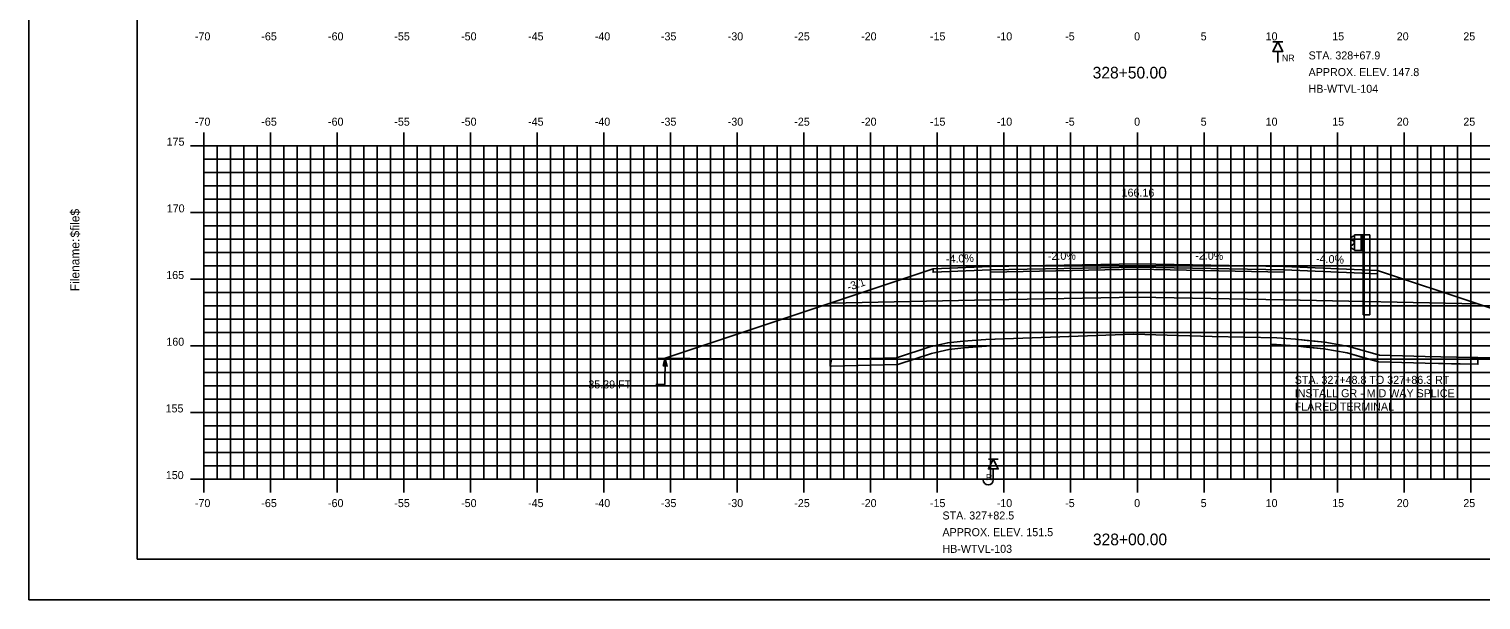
# Model space of a CAD drawing. Extents: x 1140981 to 1141151, y 608981 to 609091.
# Drawn here: x 1140980.7 to 1141089.5, y 608981.3 to 609024.1 of the extents above; entities that cross this region are included whole.
import ezdxf

# ---------------------------------------------------------------- set-up
doc = ezdxf.new("R2010")
doc.units = 0
for name, color, linetype in [('ANNOTATION', 7, 'Continuous'), ('BORDER', 7, 'Continuous'), ('D_Guardrail_Beam_Rt', 7, 'Continuous'), ('D_Guardrail_ConcBarrier', 7, 'Continuous'), ('D_Roadway_Centerline', 7, 'Continuous'), ('D_Roadway_Centerline_Text', 7, 'Continuous'), ('D_Roadway_Edge_Shoulder', 7, 'Continuous'), ('D_Roadway_Edge_TW', 7, 'Continuous'), ('D_Roadway_Pavement', 7, 'Continuous'), ('D_Roadway_SlopeLines', 7, 'Continuous'), ('D_Roadway_SubGrade', 7, 'Continuous'), ('D_Text_Standard', 7, 'Continuous'), ('H_V ANNOTATION', 7, 'Continuous'), ('MAJOR', 7, 'Continuous'), ('MINOR', 7, 'Continuous'), ('PLOT BOUNDARY', 7, 'Continuous'), ('ROCKS', 7, 'Continuous'), ('S_Roadway_Centerline', 7, 'Continuous'), ('SHADING', 7, 'Continuous')]:
    doc.layers.add(name, color=color, linetype=linetype)

msp = doc.modelspace()

# ---------------------------------------------------------------- linework, layer by layer
msp.add_lwpolyline([(1141028.37, 608999.41), (1141037.74, 609002.53), (1141040.74, 609003.53), (1141048.45, 609006.1), (1141048.45, 609006.1), (1141052.76, 609006.27), (1141063.76, 609006.49), (1141074.76, 609006.27), (1141081.76, 609005.99), (1141089.29, 609003.48), (1141092.29, 609002.48), (1141100.31, 608999.81)])
at = {"layer": 'BORDER'}
msp.add_lwpolyline([(1140988.76, 608984.34), (1141148.76, 608984.34), (1141148.76, 609089.34), (1140988.76, 609089.34)], close=True, dxfattribs=at)
at = {"layer": 'D_Guardrail_Beam_Rt'}
for p, q in [((1141079.94, 609008.55), (1141079.79, 609008.45)), ((1141079.79, 609008.31), (1141079.99, 609008.17)), ((1141080.03, 609008.57), (1141079.95, 609008.56)), ((1141079.99, 609007.97), (1141079.79, 609007.84)), ((1141079.79, 609007.69), (1141079.94, 609007.59)), ((1141079.95, 609007.59), (1141080.03, 609007.57)), ((1141080.02, 609008.11), (1141080.02, 609008.04))]:
    msp.add_line(p, q, dxfattribs=at)
for centre, major_axis, start_param, end_param in [((1141079.85, 609008.38), (-0.0877, 0), 5.323254, 7.243116), ((1141079.96, 609008.52), (-0.0417, 0), 4.907132, 5.323254), ((1141079.85, 609007.77), (-0.0877, 0), 5.323254, 7.243116), ((1141079.96, 609007.63), (-0.0417, 0), 0.959931, 1.376053), ((1141079.95, 609008.11), (0.0789, 0), 0, 0.959931), ((1141079.95, 609008.04), (0.0789, 0), 5.323254, 6.283185)]:
    msp.add_ellipse(centre, major_axis=major_axis, ratio=0.995501, start_param=start_param, end_param=end_param, dxfattribs=at)
at = {"layer": 'D_Guardrail_ConcBarrier'}
for p, q in [((1141080.03, 609008.66), (1141080.72, 609008.66)), ((1141080.03, 609007.49), (1141080.03, 609008.66)), ((1141080.55, 609008.66), (1141080.55, 609007.49)), ((1141080.65, 609008.66), (1141080.65, 609007.49)), ((1141080.72, 609008.66), (1141081.19, 609008.66)), ((1141080.72, 609008.66), (1141080.72, 609007.49)), ((1141081.19, 609008.66), (1141081.19, 609002.66)), ((1141080.72, 609007.49), (1141080.03, 609007.49)), ((1141080.7, 609002.66), (1141080.7, 609007.49)), ((1141080.7, 609002.66), (1141081.19, 609002.66))]:
    msp.add_line(p, q, dxfattribs=at)
at = {"layer": 'D_Roadway_Edge_Shoulder'}
for points in [[(1141052.76, 609006.27), (1141048.45, 609006.1), (1141048.45, 609005.85), (1141052.76, 609006.02)], [(1141074.76, 609006.27), (1141081.76, 609005.99), (1141081.76, 609005.74), (1141074.76, 609006.02)]]:
    msp.add_lwpolyline(points, close=True, dxfattribs=at)
at = {"layer": 'D_Roadway_Edge_TW'}
msp.add_lwpolyline([(1141052.76, 609006.02), (1141052.76, 609006.27), (1141063.76, 609006.49), (1141074.76, 609006.27), (1141074.76, 609006.02), (1141063.76, 609006.24)], close=True, dxfattribs=at)
at = {"layer": 'D_Roadway_Pavement'}
msp.add_lwpolyline([(1141052.76, 609005.86), (1141052.76, 609006.02), (1141063.76, 609006.24), (1141074.76, 609006.02), (1141074.76, 609005.86), (1141063.76, 609006.08)], close=True, dxfattribs=at)
at = {"layer": 'D_Roadway_SlopeLines'}
for p, q in [((1141053.76, 609000.87), (1141053.76, 609000.37)), ((1141073.76, 609000.95), (1141073.76, 609000.45)), ((1141040.74, 608999.3), (1141040.74, 608998.8)), ((1141089.29, 608999.45), (1141089.29, 608998.95))]:
    msp.add_line(p, q, dxfattribs=at)
for points in [[(1141040.74, 609003.53), (1141037.74, 609002.53)], [(1141089.29, 609003.48), (1141092.29, 609002.48)], [(1141037.74, 609002.53), (1141028.37, 608999.41)], [(1141040.74, 608998.8), (1141040.83, 608998.8), (1141045.8, 608998.94), (1141048.32, 608999.77), (1141049.63, 609000.07), (1141050.76, 609000.19), (1141052.44, 609000.32), (1141053.76, 609000.37)], [(1141073.76, 609000.45), (1141074.2, 609000.44), (1141075.58, 609000.33), (1141077.75, 609000.11), (1141079.5, 608999.8), (1141081.84, 608999.13), (1141085.34, 608999.03), (1141089.29, 608998.95)]]:
    msp.add_lwpolyline(points, dxfattribs=at)
at = {"layer": 'D_Roadway_SubGrade'}
for points in [[(1141052.76, 609005.86), (1141052.76, 609006.02), (1141048.45, 609005.85), (1141048.45, 609006.1), (1141048.45, 609006.1), (1141040.74, 609003.53), (1141052.76, 609003.77)], [(1141052.76, 609003.77), (1141052.76, 609005.86), (1141063.76, 609006.08), (1141074.76, 609005.86), (1141074.76, 609003.77), (1141063.76, 609003.99)], [(1141074.76, 609005.86), (1141074.76, 609006.02), (1141081.76, 609005.74), (1141081.76, 609005.99), (1141081.76, 609005.99), (1141089.29, 609003.48), (1141074.76, 609003.77)]]:
    msp.add_lwpolyline(points, close=True, dxfattribs=at)
at = {"layer": 'D_Text_Standard'}
msp.add_lwpolyline([(1141028.37, 608999.41), (1141028.34, 608997.44), (1141027.66, 608997.44)], dxfattribs=at)
msp.add_lwpolyline([(1141028.37, 608999.41), (1141028.51, 608998.82), (1141028.22, 608998.83)], close=True, dxfattribs=at)
at = {"layer": 'MAJOR'}
for p, q in [((1140993.76, 609016.34), (1140993.76, 609015.34)), ((1140998.76, 609016.34), (1140998.76, 609015.34)), ((1141003.76, 609016.34), (1141003.76, 609015.34)), ((1141008.76, 609016.34), (1141008.76, 609015.34)), ((1141013.76, 609016.34), (1141013.76, 609015.34)), ((1141018.76, 609016.34), (1141018.76, 609015.34)), ((1141023.76, 609016.34), (1141023.76, 609015.34)), ((1141028.76, 609016.34), (1141028.76, 609015.34)), ((1141033.76, 609016.34), (1141033.76, 609015.34)), ((1141038.76, 609016.34), (1141038.76, 609015.34)), ((1141043.76, 609016.34), (1141043.76, 609015.34)), ((1141048.76, 609016.34), (1141048.76, 609015.34)), ((1141053.76, 609016.34), (1141053.76, 609015.34)), ((1141058.76, 609016.34), (1141058.76, 609015.34)), ((1141063.76, 609016.34), (1141063.76, 609015.34)), ((1141068.76, 609016.34), (1141068.76, 609015.34)), ((1141073.76, 609016.34), (1141073.76, 609015.34)), ((1141078.76, 609016.34), (1141078.76, 609015.34)), ((1141083.76, 609016.34), (1141083.76, 609015.34)), ((1141088.76, 609016.34), (1141088.76, 609015.34)), ((1140992.76, 609015.34), (1140993.76, 609015.34)), ((1140993.76, 609015.34), (1141133.76, 609015.34)), ((1140993.76, 608990.34), (1140993.76, 609015.34)), ((1140993.76, 608990.34), (1140993.76, 609015.34)), ((1140993.76, 609015.34), (1141133.76, 609015.34)), ((1140998.76, 608990.34), (1140998.76, 609015.34)), ((1141003.76, 608990.34), (1141003.76, 609015.34)), ((1141008.76, 608990.34), (1141008.76, 609015.34)), ((1141013.76, 608990.34), (1141013.76, 609015.34)), ((1141018.76, 608990.34), (1141018.76, 609015.34)), ((1141023.76, 608990.34), (1141023.76, 609015.34)), ((1141028.76, 608990.34), (1141028.76, 609015.34)), ((1141033.76, 608990.34), (1141033.76, 609015.34)), ((1141038.76, 608990.34), (1141038.76, 609015.34)), ((1141043.76, 608990.34), (1141043.76, 609015.34)), ((1141048.76, 608990.34), (1141048.76, 609015.34)), ((1141053.76, 608990.34), (1141053.76, 609015.34)), ((1141058.76, 608990.34), (1141058.76, 609015.34)), ((1141063.76, 608990.34), (1141063.76, 609015.34)), ((1141068.76, 608990.34), (1141068.76, 609015.34)), ((1141073.76, 608990.34), (1141073.76, 609015.34)), ((1141078.76, 608990.34), (1141078.76, 609015.34)), ((1141083.76, 608990.34), (1141083.76, 609015.34)), ((1141088.76, 608990.34), (1141088.76, 609015.34)), ((1140992.76, 609010.34), (1140993.76, 609010.34)), ((1140993.76, 609010.34), (1141133.76, 609010.34)), ((1140992.76, 609005.34), (1140993.76, 609005.34)), ((1140993.76, 609005.34), (1141133.76, 609005.34)), ((1140992.76, 609000.34), (1140993.76, 609000.34)), ((1140993.76, 609000.34), (1141133.76, 609000.34)), ((1140992.76, 608995.34), (1140993.76, 608995.34)), ((1140993.76, 608995.34), (1141133.76, 608995.34)), ((1140992.76, 608990.34), (1140993.76, 608990.34)), ((1140993.76, 608990.34), (1141133.76, 608990.34)), ((1140993.76, 608990.34), (1141133.76, 608990.34)), ((1140993.76, 608989.33), (1140993.76, 608990.34)), ((1140998.76, 608989.33), (1140998.76, 608990.34)), ((1141003.76, 608989.33), (1141003.76, 608990.34)), ((1141008.76, 608989.33), (1141008.76, 608990.34)), ((1141013.76, 608989.33), (1141013.76, 608990.34)), ((1141018.76, 608989.33), (1141018.76, 608990.34)), ((1141023.76, 608989.33), (1141023.76, 608990.34)), ((1141028.76, 608989.33), (1141028.76, 608990.34)), ((1141033.76, 608989.33), (1141033.76, 608990.34)), ((1141038.76, 608989.33), (1141038.76, 608990.34)), ((1141043.76, 608989.33), (1141043.76, 608990.34)), ((1141048.76, 608989.33), (1141048.76, 608990.34)), ((1141053.76, 608989.33), (1141053.76, 608990.34)), ((1141058.76, 608989.33), (1141058.76, 608990.34)), ((1141063.76, 608989.33), (1141063.76, 608990.34)), ((1141068.76, 608989.33), (1141068.76, 608990.34)), ((1141073.76, 608989.33), (1141073.76, 608990.34)), ((1141078.76, 608989.33), (1141078.76, 608990.34)), ((1141083.76, 608989.33), (1141083.76, 608990.34)), ((1141088.76, 608989.33), (1141088.76, 608990.34))]:
    msp.add_line(p, q, dxfattribs=at)
at = {"layer": 'MINOR'}
for p, q in [((1140994.76, 608990.34), (1140994.76, 609015.34)), ((1140995.76, 608990.34), (1140995.76, 609015.34)), ((1140996.76, 608990.34), (1140996.76, 609015.34)), ((1140997.76, 608990.34), (1140997.76, 609015.34)), ((1140999.76, 608990.34), (1140999.76, 609015.34)), ((1141000.76, 608990.34), (1141000.76, 609015.34)), ((1141001.76, 608990.34), (1141001.76, 609015.34)), ((1141002.76, 608990.34), (1141002.76, 609015.34)), ((1141004.76, 608990.34), (1141004.76, 609015.34)), ((1141005.76, 608990.34), (1141005.76, 609015.34)), ((1141006.76, 608990.34), (1141006.76, 609015.34)), ((1141007.76, 608990.34), (1141007.76, 609015.34)), ((1141009.76, 608990.34), (1141009.76, 609015.34)), ((1141010.76, 608990.34), (1141010.76, 609015.34)), ((1141011.76, 608990.34), (1141011.76, 609015.34)), ((1141012.76, 608990.34), (1141012.76, 609015.34)), ((1141014.76, 608990.34), (1141014.76, 609015.34)), ((1141015.76, 608990.34), (1141015.76, 609015.34)), ((1141016.76, 608990.34), (1141016.76, 609015.34)), ((1141017.76, 608990.34), (1141017.76, 609015.34)), ((1141019.76, 608990.34), (1141019.76, 609015.34)), ((1141020.76, 608990.34), (1141020.76, 609015.34)), ((1141021.76, 608990.34), (1141021.76, 609015.34)), ((1141022.76, 608990.34), (1141022.76, 609015.34)), ((1141024.76, 608990.34), (1141024.76, 609015.34)), ((1141025.76, 608990.34), (1141025.76, 609015.34)), ((1141026.76, 608990.34), (1141026.76, 609015.34)), ((1141027.76, 608990.34), (1141027.76, 609015.34)), ((1141029.76, 608990.34), (1141029.76, 609015.34)), ((1141030.76, 608990.34), (1141030.76, 609015.34)), ((1141031.76, 608990.34), (1141031.76, 609015.34)), ((1141032.76, 608990.34), (1141032.76, 609015.34)), ((1141034.76, 608990.34), (1141034.76, 609015.34)), ((1141035.76, 608990.34), (1141035.76, 609015.34)), ((1141036.76, 608990.34), (1141036.76, 609015.34)), ((1141037.76, 608990.34), (1141037.76, 609015.34)), ((1141039.76, 608990.34), (1141039.76, 609015.34)), ((1141040.76, 608990.34), (1141040.76, 609015.34)), ((1141041.76, 608990.34), (1141041.76, 609015.34)), ((1141042.76, 608990.34), (1141042.76, 609015.34)), ((1141044.76, 608990.34), (1141044.76, 609015.34)), ((1141045.76, 608990.34), (1141045.76, 609015.34)), ((1141046.76, 608990.34), (1141046.76, 609015.34)), ((1141047.76, 608990.34), (1141047.76, 609015.34)), ((1141049.76, 608990.34), (1141049.76, 609015.34)), ((1141050.76, 608990.34), (1141050.76, 609015.34)), ((1141051.76, 608990.34), (1141051.76, 609015.34)), ((1141052.76, 608990.34), (1141052.76, 609015.34)), ((1141054.76, 608990.34), (1141054.76, 609015.34)), ((1141055.76, 608990.34), (1141055.76, 609015.34)), ((1141056.76, 608990.34), (1141056.76, 609015.34)), ((1141057.76, 608990.34), (1141057.76, 609015.34)), ((1141059.76, 608990.34), (1141059.76, 609015.34)), ((1141060.76, 608990.34), (1141060.76, 609015.34)), ((1141061.76, 608990.34), (1141061.76, 609015.34)), ((1141062.76, 608990.34), (1141062.76, 609015.34)), ((1141064.76, 608990.34), (1141064.76, 609015.34)), ((1141065.76, 608990.34), (1141065.76, 609015.34)), ((1141066.76, 608990.34), (1141066.76, 609015.34)), ((1141067.76, 608990.34), (1141067.76, 609015.34)), ((1141069.76, 608990.34), (1141069.76, 609015.34)), ((1141070.76, 608990.34), (1141070.76, 609015.34)), ((1141071.76, 608990.34), (1141071.76, 609015.34)), ((1141072.76, 608990.34), (1141072.76, 609015.34)), ((1141074.76, 608990.34), (1141074.76, 609015.34)), ((1141075.76, 608990.34), (1141075.76, 609015.34)), ((1141076.76, 608990.34), (1141076.76, 609015.34)), ((1141077.76, 608990.34), (1141077.76, 609015.34)), ((1141079.76, 608990.34), (1141079.76, 609015.34)), ((1141080.76, 608990.34), (1141080.76, 609015.34)), ((1141081.76, 608990.34), (1141081.76, 609015.34)), ((1141082.76, 608990.34), (1141082.76, 609015.34)), ((1141084.76, 608990.34), (1141084.76, 609015.34)), ((1141085.76, 608990.34), (1141085.76, 609015.34)), ((1141086.76, 608990.34), (1141086.76, 609015.34)), ((1141087.76, 608990.34), (1141087.76, 609015.34)), ((1140993.76, 609014.34), (1141133.76, 609014.34)), ((1140993.76, 609014.34), (1140994.76, 609014.34)), ((1140993.76, 609013.34), (1141133.76, 609013.34)), ((1140993.76, 609013.34), (1140994.76, 609013.34)), ((1140993.76, 609012.34), (1141133.76, 609012.34)), ((1140993.76, 609012.34), (1140994.76, 609012.34)), ((1140993.76, 609011.34), (1141133.76, 609011.34)), ((1140993.76, 609011.34), (1140994.76, 609011.34)), ((1140993.76, 609009.34), (1141133.76, 609009.34)), ((1140993.76, 609009.34), (1140994.76, 609009.34)), ((1140993.76, 609008.34), (1141133.76, 609008.34)), ((1140993.76, 609008.34), (1140994.76, 609008.34)), ((1140993.76, 609007.34), (1141133.76, 609007.34)), ((1140993.76, 609007.34), (1140994.76, 609007.34)), ((1140993.76, 609006.34), (1141133.76, 609006.34)), ((1140993.76, 609006.34), (1140994.76, 609006.34)), ((1140993.76, 609004.34), (1141133.76, 609004.34)), ((1140993.76, 609004.34), (1140994.76, 609004.34)), ((1140993.76, 609003.34), (1141133.76, 609003.34)), ((1140993.76, 609003.34), (1140994.76, 609003.34)), ((1140993.76, 609002.34), (1141133.76, 609002.34)), ((1140993.76, 609002.34), (1140994.76, 609002.34)), ((1140993.76, 609001.34), (1141133.76, 609001.34)), ((1140993.76, 609001.34), (1140994.76, 609001.34)), ((1140993.76, 608999.34), (1141133.76, 608999.34)), ((1140993.76, 608999.34), (1140994.76, 608999.34)), ((1140993.76, 608998.34), (1141133.76, 608998.34)), ((1140993.76, 608998.34), (1140994.76, 608998.34)), ((1140993.76, 608997.34), (1141133.76, 608997.34)), ((1140993.76, 608997.34), (1140994.76, 608997.34)), ((1140993.76, 608996.34), (1141133.76, 608996.34)), ((1140993.76, 608996.34), (1140994.76, 608996.34)), ((1140993.76, 608994.34), (1141133.76, 608994.34)), ((1140993.76, 608994.34), (1140994.76, 608994.34)), ((1140993.76, 608993.34), (1141133.76, 608993.34)), ((1140993.76, 608993.34), (1140994.76, 608993.34)), ((1140993.76, 608992.34), (1141133.76, 608992.34)), ((1140993.76, 608992.34), (1140994.76, 608992.34)), ((1140993.76, 608991.34), (1141133.76, 608991.34)), ((1140993.76, 608991.34), (1140994.76, 608991.34))]:
    msp.add_line(p, q, dxfattribs=at)
at = {"layer": 'PLOT BOUNDARY'}
msp.add_lwpolyline([(1140980.66, 608981.28), (1141150.66, 608981.28), (1141150.66, 609091.28), (1140980.66, 609091.28)], close=True, dxfattribs=at)
at = {"layer": 'ROCKS'}
for p, q in [((1141074.66, 609023.14), (1141073.92, 609023.14)), ((1141074.29, 609022.4), (1141074.29, 609021.59)), ((1141053.33, 608991.84), (1141052.59, 608991.84)), ((1141052.96, 608991.1), (1141052.96, 608990.28))]:
    msp.add_line(p, q, dxfattribs=at)
for points in [[(1141074.29, 609023.14), (1141074.66, 609022.4), (1141073.92, 609022.4)], [(1141052.96, 608991.84), (1141053.33, 608991.1), (1141052.59, 608991.1)]]:
    msp.add_lwpolyline(points, close=True, dxfattribs=at)
msp.add_arc((1141052.58, 608990.28), 0.373, 180, 0, dxfattribs=at)
at = {"layer": 'S_Roadway_Centerline'}
msp.add_lwpolyline([(1141027.79, 608999.42), (1141035.02, 608999.33), (1141040.82, 608999.3), (1141045.71, 608999.44), (1141048.19, 609000.26), (1141049.55, 609000.56), (1141050.71, 609000.69), (1141052.41, 609000.82), (1141057.26, 609000.98), (1141063.48, 609001.22), (1141069.36, 609001.03), (1141074.22, 609000.94), (1141075.62, 609000.83), (1141077.82, 609000.61), (1141079.61, 609000.29), (1141081.91, 608999.63), (1141085.35, 608999.53), (1141090.01, 608999.43), (1141098.33, 608999.82), (1141111.2, 608999.73)], dxfattribs=at)
at = {"layer": 'SHADING'}
for p, q in [((1141053.76, 609000.37), (1141053.76, 609000.87)), ((1141040.82, 608999.3), (1141040.74, 608998.8))]:
    msp.add_line(p, q, dxfattribs=at)
for points in [[(1141053.76, 609000.87), (1141052.41, 609000.82), (1141050.71, 609000.69), (1141049.55, 609000.56), (1141048.19, 609000.26), (1141045.71, 608999.44), (1141040.82, 608999.3)], [(1141040.74, 608998.8), (1141045.8, 608998.94), (1141048.32, 608999.77), (1141049.63, 609000.07), (1141050.76, 609000.19), (1141052.44, 609000.32), (1141053.76, 609000.37)]]:
    msp.add_lwpolyline(points, dxfattribs=at)
msp.add_lwpolyline([(1141073.76, 609000.95), (1141073.76, 609000.45), (1141074.2, 609000.44), (1141075.58, 609000.33), (1141076.66, 609000.22), (1141077.75, 609000.11), (1141079.5, 608999.8), (1141080.67, 608999.47), (1141081.84, 608999.13), (1141083.59, 608999.08), (1141085.34, 608999.03), (1141087.31, 608998.99), (1141089.29, 608998.95), (1141089.29, 608999.45), (1141087.68, 608999.48), (1141085.35, 608999.53), (1141083.63, 608999.58), (1141081.91, 608999.63), (1141079.61, 609000.29), (1141077.82, 609000.61), (1141076.72, 609000.72), (1141075.62, 609000.83), (1141074.22, 609000.94)], close=True, dxfattribs=at)

# ---------------------------------------------------------------- texts
at = {"layer": 'ANNOTATION'}
for s, rotation, p in [('-4.0%', 2.2906, (1141049.42, 609006.54)), ('-2.0%', 1.1458, (1141057.06, 609006.76)), ('-2.0%', 358.8542, (1141068.1, 609006.81)), ('-4.0%', 357.7094, (1141077.15, 609006.58)), ('-3:1', 18.4348, (1141042.11, 609004.44))]:
    msp.add_text(s, height=0.6, rotation=rotation, dxfattribs=at).set_placement(p)
for s, p in [('STA. 327+48.8 TO 327+86.3 RT', (1141075.56, 608997.48)), ('INSTALL GR - MID WAY SPLICE', (1141075.56, 608996.48)), ('FLARED TERMINAL', (1141075.56, 608995.48))]:
    msp.add_text(s, height=0.6, dxfattribs=at).set_placement(p)
at = {"layer": 'BORDER'}
for s, p in [('$file$', (1140984.44, 609008.46)), ('Filename:', (1140984.44, 609004.43))]:
    msp.add_text(s, height=0.67, rotation=90, dxfattribs=at).set_placement(p)
at = {"layer": 'D_Roadway_Centerline'}
for s, p in [('C', (1141063.75, 609006.49)), ('C', (1141063.75, 609006.49)), ('L', (1141063.76, 609006.49)), ('L', (1141063.76, 609006.49))]:
    msp.add_text(s, height=0.0146, dxfattribs=at).set_placement(p)
at = {"layer": 'D_Roadway_Centerline_Text'}
msp.add_text('166.16', height=0.6, dxfattribs=at).set_placement((1141062.58, 609011.52))
at = {"layer": 'D_Text_Standard'}
msp.add_text('-35.39 FT', height=0.6, dxfattribs=at).set_placement((1141022.33, 608997.14))
at = {"layer": 'H_V ANNOTATION'}
for s, height, p in [('-70', 0.6, (1140993.1, 609023.24)), ('-65', 0.6, (1140998.08, 609023.24)), ('-60', 0.6, (1141003.08, 609023.24)), ('-55', 0.6, (1141008.05, 609023.24)), ('-50', 0.6, (1141013.06, 609023.24)), ('-45', 0.6, (1141018.08, 609023.24)), ('-40', 0.6, (1141023.08, 609023.24)), ('-35', 0.6, (1141028.04, 609023.24)), ('-30', 0.6, (1141033.05, 609023.24)), ('-25', 0.6, (1141038.04, 609023.24)), ('-20', 0.6, (1141043.05, 609023.24)), ('-15', 0.6, (1141048.21, 609023.24)), ('-10', 0.6, (1141053.22, 609023.24)), ('-5', 0.6, (1141058.35, 609023.24)), ('0', 0.6, (1141063.52, 609023.24)), ('5', 0.6, (1141068.51, 609023.24)), ('10', 0.6, (1141073.38, 609023.24)), ('15', 0.6, (1141078.37, 609023.24)), ('20', 0.6, (1141083.21, 609023.24)), ('25', 0.6, (1141088.2, 609023.24)), ('328+50.00', 0.875, (1141060.41, 609020.38)), ('-70', 0.6, (1140993.1, 609016.84)), ('-65', 0.6, (1140998.08, 609016.84)), ('-60', 0.6, (1141003.08, 609016.84)), ('-55', 0.6, (1141008.05, 609016.84)), ('-50', 0.6, (1141013.06, 609016.84)), ('-45', 0.6, (1141018.08, 609016.84)), ('-40', 0.6, (1141023.08, 609016.84)), ('-35', 0.6, (1141028.04, 609016.84)), ('-30', 0.6, (1141033.05, 609016.84)), ('-25', 0.6, (1141038.04, 609016.84)), ('-20', 0.6, (1141043.05, 609016.84)), ('-15', 0.6, (1141048.21, 609016.84)), ('-10', 0.6, (1141053.22, 609016.84)), ('-5', 0.6, (1141058.35, 609016.84)), ('0', 0.6, (1141063.52, 609016.84)), ('5', 0.6, (1141068.51, 609016.84)), ('10', 0.6, (1141073.38, 609016.84)), ('15', 0.6, (1141078.37, 609016.84)), ('20', 0.6, (1141083.21, 609016.84)), ('25', 0.6, (1141088.2, 609016.84)), ('175', 0.6, (1140990.98, 609015.34)), ('170', 0.6, (1140990.99, 609010.34)), ('165', 0.6, (1140990.95, 609005.34)), ('160', 0.6, (1140990.96, 609000.34)), ('155', 0.6, (1140990.9, 608995.34)), ('150', 0.6, (1140990.92, 608990.34)), ('-70', 0.6, (1140993.1, 608988.24)), ('-65', 0.6, (1140998.08, 608988.24)), ('-60', 0.6, (1141003.08, 608988.24)), ('-55', 0.6, (1141008.05, 608988.24)), ('-50', 0.6, (1141013.06, 608988.24)), ('-45', 0.6, (1141018.08, 608988.24)), ('-40', 0.6, (1141023.08, 608988.24)), ('-35', 0.6, (1141028.04, 608988.24)), ('-30', 0.6, (1141033.05, 608988.24)), ('-25', 0.6, (1141038.04, 608988.24)), ('-20', 0.6, (1141043.05, 608988.24)), ('-15', 0.6, (1141048.21, 608988.24)), ('-10', 0.6, (1141053.22, 608988.24)), ('-5', 0.6, (1141058.35, 608988.24)), ('0', 0.6, (1141063.52, 608988.24)), ('5', 0.6, (1141068.51, 608988.24)), ('10', 0.6, (1141073.38, 608988.24)), ('15', 0.6, (1141078.37, 608988.24)), ('20', 0.6, (1141083.21, 608988.24)), ('25', 0.6, (1141088.2, 608988.24)), ('328+00.00', 0.875, (1141060.43, 608985.38))]:
    msp.add_text(s, height=height, dxfattribs=at).set_placement(p)
at = {"layer": 'MAJOR'}
msp.add_text('-', height=0.006, dxfattribs=at).set_placement((1140993.75, 608990.34))
at = {"layer": 'ROCKS'}
for s, p in [('STA. 328+67.9', (1141076.6, 609021.81)), ('APPROX. ELEV. 147.8', (1141076.6, 609020.56)), ('HB-WTVL-104', (1141076.6, 609019.31)), ('STA. 327+82.5', (1141049.15, 608987.31)), ('APPROX. ELEV. 151.5', (1141049.15, 608986.06)), ('HB-WTVL-103', (1141049.15, 608984.81))]:
    msp.add_text(s, height=0.6, rotation=360, dxfattribs=at).set_placement(p)
for s, p in [('NR', (1141074.6, 609021.67)), ('R', (1141052.41, 608990.24))]:
    msp.add_text(s, height=0.492, dxfattribs=at).set_placement(p)
at = {"layer": 'S_Roadway_Centerline'}
for s in ['C', 'L']:
    msp.add_text(s, height=0.0146, dxfattribs=at).set_placement((1141063.48, 609001.22))

doc.saveas('drawing.dxf')
